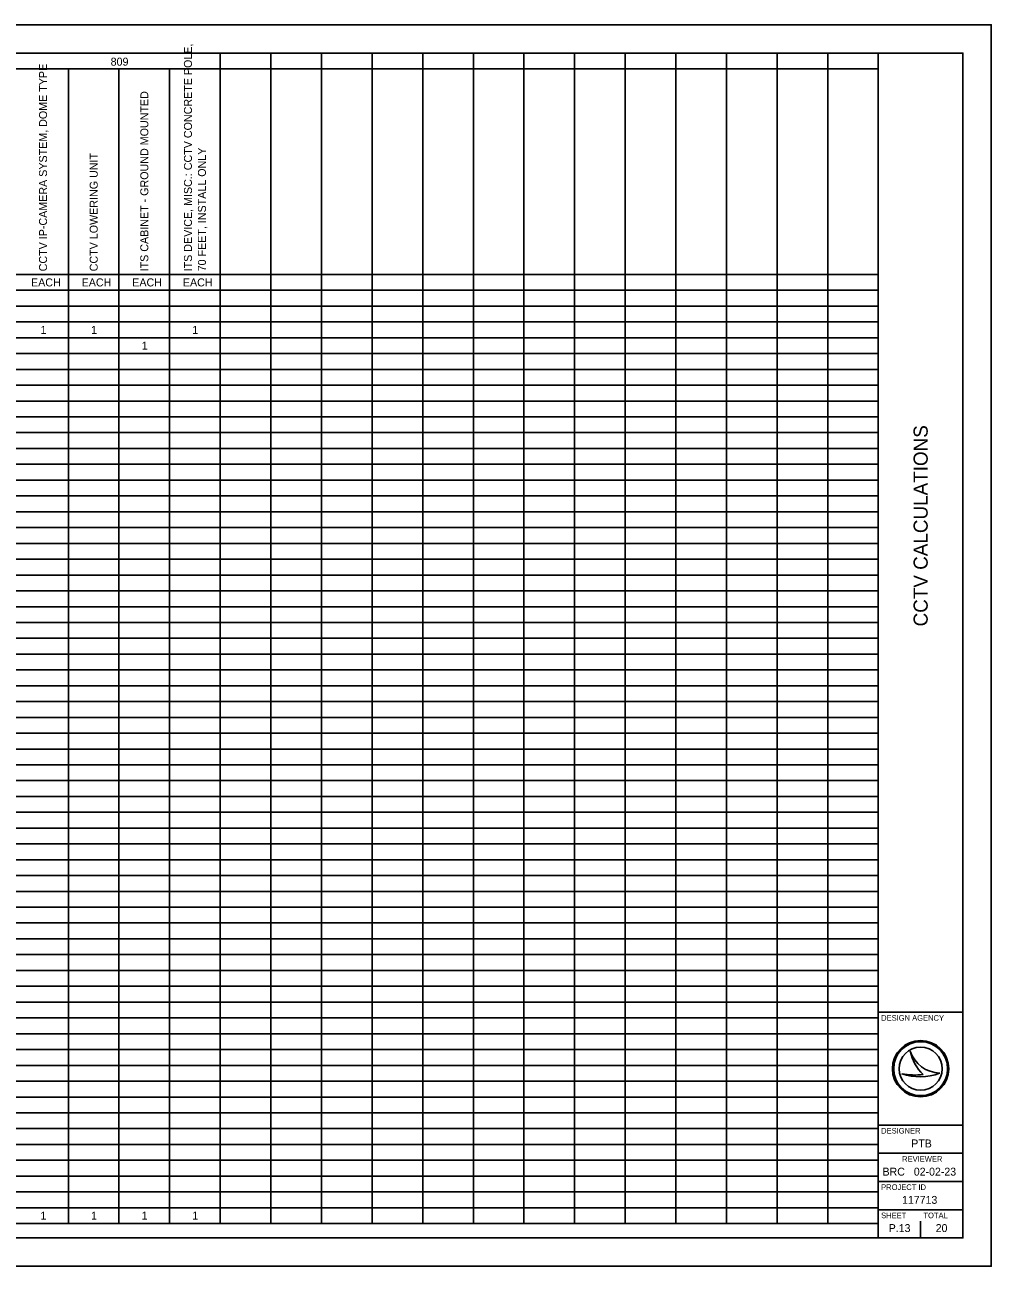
# Model space of a CAD drawing. Extents: x 0 to 34, y 0 to 22.
# Drawn here: x 16.88 to 34, y 0 to 22 of the extents above; entities that cross this region are included whole.
import ezdxf

# ---------------------------------------------------------------- set-up
doc = ezdxf.new("R2010")
doc.units = 0
for name, color, linetype in [('SH_Border', 7, 'Continuous'), ('SH_Cut_Line', 7, 'Continuous'), ('SH_Data', 7, 'Continuous'), ('SH_Text', 7, 'Continuous')]:
    doc.layers.add(name, color=color, linetype=linetype)

msp = doc.modelspace()

# ---------------------------------------------------------------- linework, layer by layer
at = {"layer": 'SH_Border'}
for p, q in [((32, 0.5), (32, 21.5)), ((32, 4.5), (33.5, 4.5)), ((32, 2.5), (33.5, 2.5)), ((32, 2), (33.5, 2)), ((32, 1.5), (33.5, 1.5)), ((32, 1), (33.5, 1))]:
    msp.add_line(p, q, dxfattribs=at)
msp.add_lwpolyline([(1.5, 21.5), (33.5, 21.5), (33.5, 0.5), (1.5, 0.5)], close=True, dxfattribs=at)
at = {"layer": 'SH_Cut_Line'}
msp.add_lwpolyline([(0, 0), (34, 0), (34, 22), (0, 22)], close=True, dxfattribs=at)
at = {"layer": 'SH_Data'}
for p, q in [((32.567, 3.81), (32.567, 3.81)), ((32.417, 3.41), (32.417, 3.41)), ((32.75, 3.5), (32.75, 3.5)), ((33.087, 3.419), (33.087, 3.419)), ((32.375, 0.675), (32.375, 0.675)), ((32.75, 0.5), (32.75, 0.8))]:
    msp.add_line(p, q, dxfattribs=at)
for radius in [0.5, 0.477, 0.477, 0.382]:
    msp.add_circle((32.75, 3.5), radius, dxfattribs=at)
for centre, radius, start, end in [((33.116, 3.998), 0.58, 198.9257, 198.9319), ((33.347, 3.97), 0.796, 191.6379, 191.6421), ((33.116, 3.998), 0.58, 198.9319, 267.1657), ((33.347, 3.97), 0.796, 191.6421, 226.0947), ((32.739, 4.37), 1.013, 251.4576, 290.0832), ((32.648, 4.654), 1.266, 259.4964, 259.4995), ((32.739, 4.37), 1.013, 251.4527, 251.4576), ((32.648, 4.654), 1.266, 259.4995, 276.6672)]:
    msp.add_arc(centre, radius, start, end, dxfattribs=at)
at = {"layer": 'SH_Text'}
for p, q in [((1.5, 21.5), (32, 21.5)), ((20.338, 21.5), (20.338, 0.756)), ((21.235, 21.5), (21.235, 0.756)), ((22.132, 21.5), (22.132, 0.756)), ((23.029, 21.5), (23.029, 0.756)), ((23.926, 21.5), (23.926, 0.756)), ((24.824, 21.5), (24.824, 0.756)), ((25.721, 21.5), (25.721, 0.756)), ((26.618, 21.5), (26.618, 0.756)), ((27.515, 21.5), (27.515, 0.756)), ((28.412, 21.5), (28.412, 0.756)), ((29.309, 21.5), (29.309, 0.756)), ((30.206, 21.5), (30.206, 0.756)), ((31.103, 21.5), (31.103, 0.756)), ((32, 21.5), (32, 0.756)), ((5.985, 21.22), (32, 21.22)), ((17.647, 21.22), (17.647, 0.756)), ((18.544, 21.22), (18.544, 0.756)), ((19.441, 21.22), (19.441, 0.756)), ((5.985, 17.575), (32, 17.575)), ((1.5, 17.295), (32, 17.295)), ((1.5, 17.015), (32, 17.015)), ((1.5, 16.734), (32, 16.734)), ((1.5, 16.454), (32, 16.454)), ((1.5, 16.174), (32, 16.174)), ((1.5, 15.893), (32, 15.893)), ((1.5, 15.613), (32, 15.613)), ((1.5, 15.333), (32, 15.333)), ((1.5, 15.052), (32, 15.052)), ((1.5, 14.772), (32, 14.772)), ((1.5, 14.492), (32, 14.492)), ((1.5, 14.211), (32, 14.211)), ((1.5, 13.931), (32, 13.931)), ((1.5, 13.651), (32, 13.651)), ((1.5, 13.37), (32, 13.37)), ((1.5, 13.09), (32, 13.09)), ((1.5, 12.81), (32, 12.81)), ((1.5, 12.529), (32, 12.529)), ((1.5, 12.249), (32, 12.249)), ((1.5, 11.969), (32, 11.969)), ((1.5, 11.688), (32, 11.688)), ((1.5, 11.408), (32, 11.408)), ((1.5, 11.128), (32, 11.128)), ((1.5, 10.847), (32, 10.847)), ((1.5, 10.567), (32, 10.567)), ((1.5, 10.287), (32, 10.287)), ((1.5, 10.006), (32, 10.006)), ((1.5, 9.726), (32, 9.726)), ((1.5, 9.446), (32, 9.446)), ((1.5, 9.165), (32, 9.165)), ((1.5, 8.885), (32, 8.885)), ((1.5, 8.605), (32, 8.605)), ((1.5, 8.324), (32, 8.324)), ((1.5, 8.044), (32, 8.044)), ((1.5, 7.764), (32, 7.764)), ((1.5, 7.483), (32, 7.483)), ((1.5, 7.203), (32, 7.203)), ((1.5, 6.923), (32, 6.923)), ((1.5, 6.642), (32, 6.642)), ((1.5, 6.362), (32, 6.362)), ((1.5, 6.082), (32, 6.082)), ((1.5, 5.801), (32, 5.801)), ((1.5, 5.521), (32, 5.521)), ((1.5, 5.241), (32, 5.241)), ((1.5, 4.96), (32, 4.96)), ((1.5, 4.68), (32, 4.68)), ((1.5, 4.4), (32, 4.4)), ((1.5, 4.119), (32, 4.119)), ((1.5, 3.839), (32, 3.839)), ((1.5, 3.559), (32, 3.559)), ((1.5, 3.278), (32, 3.278)), ((1.5, 2.998), (32, 2.998)), ((1.5, 2.718), (32, 2.718)), ((1.5, 2.438), (32, 2.438)), ((1.5, 2.157), (32, 2.157)), ((1.5, 1.877), (32, 1.877)), ((1.5, 1.597), (32, 1.597)), ((1.5, 1.316), (32, 1.316)), ((1.5, 1.036), (32, 1.036)), ((1.5, 0.756), (32, 0.756))]:
    msp.add_line(p, q, dxfattribs=at)

# ---------------------------------------------------------------- texts
at = {"layer": 'SH_Data'}
msp.add_text('CCTV CALCULATIONS', height=0.25, rotation=90, dxfattribs=at).set_placement((32.875, 11.338))
for s, height, p in [('DESIGN AGENCY', 0.1, (32.05, 4.35)), ('DESIGNER', 0.1, (32.05, 2.35)), ('PTB', 0.14, (32.584, 2.105)), ('REVIEWER', 0.1, (32.422, 1.85)), ('BRC', 0.14, (32.075, 1.605)), ('02-02-23', 0.14, (32.629, 1.605)), ('PROJECT ID', 0.1, (32.05, 1.35)), ('117713', 0.14, (32.421, 1.105)), ('SHEET', 0.1, (32.05, 0.85)), ('TOTAL', 0.1, (32.8, 0.85)), ('P.13', 0.14, (32.185, 0.605)), ('20', 0.14, (33.017, 0.605))]:
    msp.add_text(s, height=height, dxfattribs=at).set_placement(p)
at = {"layer": 'SH_Text'}
for s, p in [('ITS DEVICE, MISC.: CCTV CONCRETE POLE, ', (19.837, 17.631)), ('CCTV IP-CAMERA SYSTEM, DOME TYPE', (17.269, 17.631)), ('ITS CABINET - GROUND MOUNTED', (19.064, 17.631)), ('70 FEET, INSTALL ONLY', (20.085, 17.631)), ('CCTV LOWERING UNIT', (18.167, 17.631))]:
    msp.add_text(s, height=0.14185, rotation=90, dxfattribs=at).set_placement(p)
for s, height, p in [('809', 0.1418, (18.396, 21.276)), ('EACH', 0.1418, (16.985, 17.364)), ('EACH', 0.1418, (17.882, 17.364)), ('EACH', 0.1418, (18.779, 17.364)), ('EACH', 0.1418, (19.676, 17.364)), ('1', 0.142, (17.153, 16.523)), ('1', 0.142, (18.05, 16.523)), ('1', 0.142, (19.844, 16.523)), ('1', 0.142, (18.947, 16.243)), ('1', 0.142, (17.152, 0.825)), ('1', 0.142, (18.049, 0.825)), ('1', 0.142, (18.946, 0.825)), ('1', 0.142, (19.843, 0.825))]:
    msp.add_text(s, height=height, dxfattribs=at).set_placement(p)

doc.saveas('drawing.dxf')
